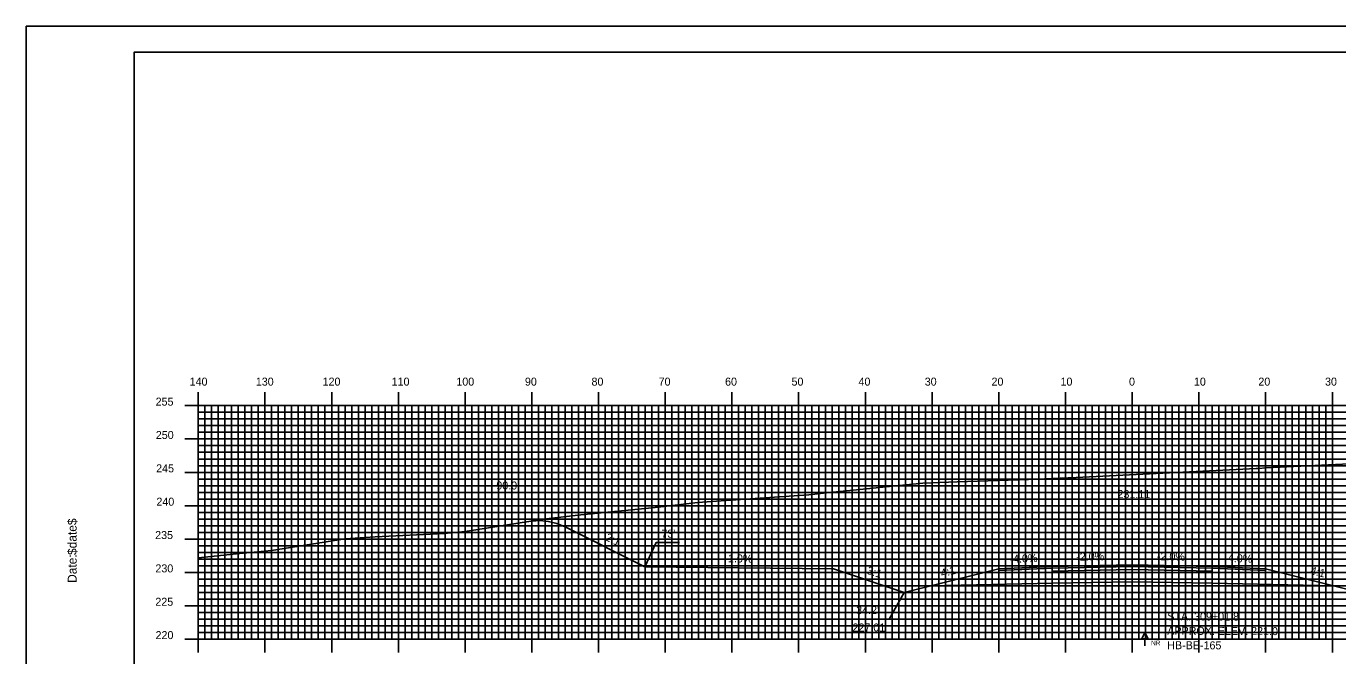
# Model space of a CAD drawing. Extents: x 1817670 to 1818013, y 442591 to 442811.
# Drawn here: x 1817669.8 to 1817866.4, y 442716.2 to 442810.5 of the extents above; entities that cross this region are included whole.
import ezdxf

# ---------------------------------------------------------------- set-up
doc = ezdxf.new("R2010")
doc.units = 0
for name, color, linetype in [('ANNOTATION', 7, 'Continuous'), ('BORDER', 7, 'Continuous'), ('BORING - NO REFUSAL', 7, 'Continuous'), ('D_Roadway_Centerline', 7, 'Continuous'), ('D_Roadway_Centerline_Text', 7, 'Continuous'), ('D_Roadway_Edge_Shoulder', 7, 'Continuous'), ('D_Roadway_Edge_TW', 7, 'Continuous'), ('D_Roadway_Pavement', 7, 'Continuous'), ('D_Roadway_SlopeLines', 7, 'Continuous'), ('D_Roadway_SubGrade', 7, 'Continuous'), ('D_Text_Standard', 7, 'Continuous'), ('H_V ANNOTATION', 7, 'Continuous'), ('MAJOR', 7, 'Continuous'), ('MINOR', 7, 'Continuous'), ('PLOT BOUNDARY', 7, 'Continuous'), ('S_Roadway_Centerline', 7, 'Continuous')]:
    doc.layers.add(name, color=color, linetype=linetype)

msp = doc.modelspace()

# ---------------------------------------------------------------- linework, layer by layer
at = {"layer": 'ANNOTATION'}
for points in [[(1817767.73, 442733.15), (1817764.23, 442733.15), (1817762.56, 442729.5)], [(1817793.49, 442721.68), (1817799.18, 442721.68), (1817801.44, 442725.67)]]:
    msp.add_lwpolyline(points, dxfattribs=at)
at = {"layer": 'BORDER'}
msp.add_lwpolyline([(1817686.01, 442596.67), (1818006.01, 442596.67), (1818006.01, 442806.67), (1817686.01, 442806.67)], close=True, dxfattribs=at)
at = {"layer": 'BORING - NO REFUSAL'}
for p, q in [((1817837.99, 442719.67), (1817837.03, 442719.67)), ((1817837.51, 442718.71), (1817837.51, 442717.65))]:
    msp.add_line(p, q, dxfattribs=at)
msp.add_lwpolyline([(1817837.51, 442719.67), (1817837.99, 442718.71), (1817837.03, 442718.71)], close=True, dxfattribs=at)
at = {"layer": 'D_Roadway_Centerline'}
msp.add_lwpolyline([(1817745.61, 442736.37), (1817746.86, 442736.45), (1817748.11, 442736.32), (1817749.36, 442736), (1817750.61, 442735.48), (1817762.56, 442729.5), (1817790.81, 442729.22), (1817801.44, 442725.67), (1817805.44, 442726.67), (1817815.61, 442729.22), (1817823.61, 442729.54), (1817835.61, 442729.78), (1817847.61, 442729.54), (1817855.61, 442729.22), (1817865.79, 442726.67), (1817869.79, 442725.67), (1817880.42, 442729.22), (1817887.92, 442729.29), (1817920.61, 442745.64), (1817921.86, 442746.19), (1817923.11, 442746.59), (1817924.36, 442746.83), (1817925.61, 442746.93)], dxfattribs=at)
at = {"layer": 'D_Roadway_Edge_Shoulder'}
for points in [[(1817823.61, 442729.54), (1817815.61, 442729.22), (1817815.61, 442728.97), (1817823.61, 442729.29)], [(1817847.61, 442729.54), (1817855.61, 442729.22), (1817855.61, 442728.97), (1817847.61, 442729.29)]]:
    msp.add_lwpolyline(points, close=True, dxfattribs=at)
at = {"layer": 'D_Roadway_Edge_TW'}
msp.add_lwpolyline([(1817823.61, 442729.29), (1817823.61, 442729.54), (1817835.61, 442729.78), (1817847.61, 442729.54), (1817847.61, 442729.29), (1817835.61, 442729.53)], close=True, dxfattribs=at)
at = {"layer": 'D_Roadway_Pavement'}
msp.add_lwpolyline([(1817823.61, 442728.87), (1817823.61, 442729.29), (1817835.61, 442729.53), (1817847.61, 442729.29), (1817847.61, 442728.87), (1817835.61, 442729.11)], close=True, dxfattribs=at)
at = {"layer": 'D_Roadway_SlopeLines'}
for points in [[(1817790.81, 442729.22), (1817762.56, 442729.5), (1817750.61, 442735.48), (1817749.36, 442736), (1817748.11, 442736.32), (1817746.86, 442736.45), (1817745.61, 442736.37)], [(1817801.44, 442725.67), (1817790.81, 442729.22)], [(1817815.61, 442729.22), (1817801.44, 442725.67)], [(1817855.61, 442729.22), (1817869.79, 442725.67)]]:
    msp.add_lwpolyline(points, dxfattribs=at)
at = {"layer": 'D_Roadway_SubGrade'}
msp.add_lwpolyline([(1817823.61, 442727.04), (1817805.44, 442726.67), (1817815.61, 442729.22), (1817815.61, 442728.97), (1817823.61, 442729.29), (1817835.61, 442729.53), (1817847.61, 442729.29), (1817855.61, 442728.97), (1817855.61, 442729.22), (1817865.79, 442726.67), (1817847.61, 442727.04), (1817835.61, 442727.28)], close=True, dxfattribs=at)
at = {"layer": 'MAJOR'}
for p, q in [((1817695.61, 442755.67), (1817695.61, 442753.67)), ((1817705.61, 442755.67), (1817705.61, 442753.67)), ((1817715.61, 442755.67), (1817715.61, 442753.67)), ((1817725.61, 442755.67), (1817725.61, 442753.67)), ((1817735.61, 442755.67), (1817735.61, 442753.67)), ((1817745.61, 442755.67), (1817745.61, 442753.67)), ((1817755.61, 442755.67), (1817755.61, 442753.67)), ((1817765.61, 442755.67), (1817765.61, 442753.67)), ((1817775.61, 442755.67), (1817775.61, 442753.67)), ((1817785.61, 442755.67), (1817785.61, 442753.67)), ((1817795.61, 442755.67), (1817795.61, 442753.67)), ((1817805.61, 442755.67), (1817805.61, 442753.67)), ((1817815.61, 442755.67), (1817815.61, 442753.67)), ((1817825.61, 442755.67), (1817825.61, 442753.67)), ((1817835.61, 442755.67), (1817835.61, 442753.67)), ((1817845.61, 442755.67), (1817845.61, 442753.67)), ((1817855.61, 442755.67), (1817855.61, 442753.67)), ((1817865.61, 442755.67), (1817865.61, 442753.67)), ((1817693.61, 442753.67), (1817695.61, 442753.67)), ((1817695.61, 442753.67), (1817975.61, 442753.67)), ((1817695.61, 442718.67), (1817695.61, 442753.67)), ((1817695.61, 442718.67), (1817695.61, 442753.67)), ((1817695.61, 442753.67), (1817975.61, 442753.67)), ((1817705.61, 442718.67), (1817705.61, 442753.67)), ((1817715.61, 442718.67), (1817715.61, 442753.67)), ((1817725.61, 442718.67), (1817725.61, 442753.67)), ((1817735.61, 442718.67), (1817735.61, 442753.67)), ((1817745.61, 442718.67), (1817745.61, 442753.67)), ((1817755.61, 442718.67), (1817755.61, 442753.67)), ((1817765.61, 442718.67), (1817765.61, 442753.67)), ((1817775.61, 442718.67), (1817775.61, 442753.67)), ((1817785.61, 442718.67), (1817785.61, 442753.67)), ((1817795.61, 442718.67), (1817795.61, 442753.67)), ((1817805.61, 442718.67), (1817805.61, 442753.67)), ((1817815.61, 442718.67), (1817815.61, 442753.67)), ((1817825.61, 442718.67), (1817825.61, 442753.67)), ((1817835.61, 442718.67), (1817835.61, 442753.67)), ((1817845.61, 442718.67), (1817845.61, 442753.67)), ((1817855.61, 442718.67), (1817855.61, 442753.67)), ((1817865.61, 442718.67), (1817865.61, 442753.67)), ((1817693.61, 442748.67), (1817695.61, 442748.67)), ((1817695.61, 442748.67), (1817975.61, 442748.67)), ((1817693.61, 442743.67), (1817695.61, 442743.67)), ((1817695.61, 442743.67), (1817975.61, 442743.67)), ((1817693.61, 442738.67), (1817695.61, 442738.67)), ((1817695.61, 442738.67), (1817975.61, 442738.67)), ((1817693.61, 442733.67), (1817695.61, 442733.67)), ((1817695.61, 442733.67), (1817975.61, 442733.67)), ((1817693.61, 442728.67), (1817695.61, 442728.67)), ((1817695.61, 442728.67), (1817975.61, 442728.67)), ((1817693.61, 442723.67), (1817695.61, 442723.67)), ((1817695.61, 442723.67), (1817975.61, 442723.67)), ((1817693.61, 442718.67), (1817695.61, 442718.67)), ((1817695.61, 442718.67), (1817975.61, 442718.67)), ((1817695.61, 442718.67), (1817975.61, 442718.67)), ((1817695.61, 442716.66), (1817695.61, 442718.67)), ((1817705.61, 442716.66), (1817705.61, 442718.67)), ((1817715.61, 442716.66), (1817715.61, 442718.67)), ((1817725.61, 442716.66), (1817725.61, 442718.67)), ((1817735.61, 442716.66), (1817735.61, 442718.67)), ((1817745.61, 442716.66), (1817745.61, 442718.67)), ((1817755.61, 442716.66), (1817755.61, 442718.67)), ((1817765.61, 442716.66), (1817765.61, 442718.67)), ((1817775.61, 442716.66), (1817775.61, 442718.67)), ((1817785.61, 442716.66), (1817785.61, 442718.67)), ((1817795.61, 442716.66), (1817795.61, 442718.67)), ((1817805.61, 442716.66), (1817805.61, 442718.67)), ((1817815.61, 442716.66), (1817815.61, 442718.67)), ((1817825.61, 442716.66), (1817825.61, 442718.67)), ((1817835.61, 442716.66), (1817835.61, 442718.67)), ((1817845.61, 442716.66), (1817845.61, 442718.67)), ((1817855.61, 442716.66), (1817855.61, 442718.67)), ((1817865.61, 442716.66), (1817865.61, 442718.67))]:
    msp.add_line(p, q, dxfattribs=at)
at = {"layer": 'MINOR'}
for p, q in [((1817696.61, 442718.67), (1817696.61, 442753.67)), ((1817697.61, 442718.67), (1817697.61, 442753.67)), ((1817698.61, 442718.67), (1817698.61, 442753.67)), ((1817699.61, 442718.67), (1817699.61, 442753.67)), ((1817700.61, 442718.67), (1817700.61, 442753.67)), ((1817701.61, 442718.67), (1817701.61, 442753.67)), ((1817702.61, 442718.67), (1817702.61, 442753.67)), ((1817703.61, 442718.67), (1817703.61, 442753.67)), ((1817704.61, 442718.67), (1817704.61, 442753.67)), ((1817706.61, 442718.67), (1817706.61, 442753.67)), ((1817707.61, 442718.67), (1817707.61, 442753.67)), ((1817708.61, 442718.67), (1817708.61, 442753.67)), ((1817709.61, 442718.67), (1817709.61, 442753.67)), ((1817710.61, 442718.67), (1817710.61, 442753.67)), ((1817711.61, 442718.67), (1817711.61, 442753.67)), ((1817712.61, 442718.67), (1817712.61, 442753.67)), ((1817713.61, 442718.67), (1817713.61, 442753.67)), ((1817714.61, 442718.67), (1817714.61, 442753.67)), ((1817716.61, 442718.67), (1817716.61, 442753.67)), ((1817717.61, 442718.67), (1817717.61, 442753.67)), ((1817718.61, 442718.67), (1817718.61, 442753.67)), ((1817719.61, 442718.67), (1817719.61, 442753.67)), ((1817720.61, 442718.67), (1817720.61, 442753.67)), ((1817721.61, 442718.67), (1817721.61, 442753.67)), ((1817722.61, 442718.67), (1817722.61, 442753.67)), ((1817723.61, 442718.67), (1817723.61, 442753.67)), ((1817724.61, 442718.67), (1817724.61, 442753.67)), ((1817726.61, 442718.67), (1817726.61, 442753.67)), ((1817727.61, 442718.67), (1817727.61, 442753.67)), ((1817728.61, 442718.67), (1817728.61, 442753.67)), ((1817729.61, 442718.67), (1817729.61, 442753.67)), ((1817730.61, 442718.67), (1817730.61, 442753.67)), ((1817731.61, 442718.67), (1817731.61, 442753.67)), ((1817732.61, 442718.67), (1817732.61, 442753.67)), ((1817733.61, 442718.67), (1817733.61, 442753.67)), ((1817734.61, 442718.67), (1817734.61, 442753.67)), ((1817736.61, 442718.67), (1817736.61, 442753.67)), ((1817737.61, 442718.67), (1817737.61, 442753.67)), ((1817738.61, 442718.67), (1817738.61, 442753.67)), ((1817739.61, 442718.67), (1817739.61, 442753.67)), ((1817740.61, 442718.67), (1817740.61, 442753.67)), ((1817741.61, 442718.67), (1817741.61, 442753.67)), ((1817742.61, 442718.67), (1817742.61, 442753.67)), ((1817743.61, 442718.67), (1817743.61, 442753.67)), ((1817744.61, 442718.67), (1817744.61, 442753.67)), ((1817746.61, 442718.67), (1817746.61, 442753.67)), ((1817747.61, 442718.67), (1817747.61, 442753.67)), ((1817748.61, 442718.67), (1817748.61, 442753.67)), ((1817749.61, 442718.67), (1817749.61, 442753.67)), ((1817750.61, 442718.67), (1817750.61, 442753.67)), ((1817751.61, 442718.67), (1817751.61, 442753.67)), ((1817752.61, 442718.67), (1817752.61, 442753.67)), ((1817753.61, 442718.67), (1817753.61, 442753.67)), ((1817754.61, 442718.67), (1817754.61, 442753.67)), ((1817756.61, 442718.67), (1817756.61, 442753.67)), ((1817757.61, 442718.67), (1817757.61, 442753.67)), ((1817758.61, 442718.67), (1817758.61, 442753.67)), ((1817759.61, 442718.67), (1817759.61, 442753.67)), ((1817760.61, 442718.67), (1817760.61, 442753.67)), ((1817761.61, 442718.67), (1817761.61, 442753.67)), ((1817762.61, 442718.67), (1817762.61, 442753.67)), ((1817763.61, 442718.67), (1817763.61, 442753.67)), ((1817764.61, 442718.67), (1817764.61, 442753.67)), ((1817766.61, 442718.67), (1817766.61, 442753.67)), ((1817767.61, 442718.67), (1817767.61, 442753.67)), ((1817768.61, 442718.67), (1817768.61, 442753.67)), ((1817769.61, 442718.67), (1817769.61, 442753.67)), ((1817770.61, 442718.67), (1817770.61, 442753.67)), ((1817771.61, 442718.67), (1817771.61, 442753.67)), ((1817772.61, 442718.67), (1817772.61, 442753.67)), ((1817773.61, 442718.67), (1817773.61, 442753.67)), ((1817774.61, 442718.67), (1817774.61, 442753.67)), ((1817776.61, 442718.67), (1817776.61, 442753.67)), ((1817777.61, 442718.67), (1817777.61, 442753.67)), ((1817778.61, 442718.67), (1817778.61, 442753.67)), ((1817779.61, 442718.67), (1817779.61, 442753.67)), ((1817780.61, 442718.67), (1817780.61, 442753.67)), ((1817781.61, 442718.67), (1817781.61, 442753.67)), ((1817782.61, 442718.67), (1817782.61, 442753.67)), ((1817783.61, 442718.67), (1817783.61, 442753.67)), ((1817784.61, 442718.67), (1817784.61, 442753.67)), ((1817786.61, 442718.67), (1817786.61, 442753.67)), ((1817787.61, 442718.67), (1817787.61, 442753.67)), ((1817788.61, 442718.67), (1817788.61, 442753.67)), ((1817789.61, 442718.67), (1817789.61, 442753.67)), ((1817790.61, 442718.67), (1817790.61, 442753.67)), ((1817791.61, 442718.67), (1817791.61, 442753.67)), ((1817792.61, 442718.67), (1817792.61, 442753.67)), ((1817793.61, 442718.67), (1817793.61, 442753.67)), ((1817794.61, 442718.67), (1817794.61, 442753.67)), ((1817796.61, 442718.67), (1817796.61, 442753.67)), ((1817797.61, 442718.67), (1817797.61, 442753.67)), ((1817798.61, 442718.67), (1817798.61, 442753.67)), ((1817799.61, 442718.67), (1817799.61, 442753.67)), ((1817800.61, 442718.67), (1817800.61, 442753.67)), ((1817801.61, 442718.67), (1817801.61, 442753.67)), ((1817802.61, 442718.67), (1817802.61, 442753.67)), ((1817803.61, 442718.67), (1817803.61, 442753.67)), ((1817804.61, 442718.67), (1817804.61, 442753.67)), ((1817806.61, 442718.67), (1817806.61, 442753.67)), ((1817807.61, 442718.67), (1817807.61, 442753.67)), ((1817808.61, 442718.67), (1817808.61, 442753.67)), ((1817809.61, 442718.67), (1817809.61, 442753.67)), ((1817810.61, 442718.67), (1817810.61, 442753.67)), ((1817811.61, 442718.67), (1817811.61, 442753.67)), ((1817812.61, 442718.67), (1817812.61, 442753.67)), ((1817813.61, 442718.67), (1817813.61, 442753.67)), ((1817814.61, 442718.67), (1817814.61, 442753.67)), ((1817816.61, 442718.67), (1817816.61, 442753.67)), ((1817817.61, 442718.67), (1817817.61, 442753.67)), ((1817818.61, 442718.67), (1817818.61, 442753.67)), ((1817819.61, 442718.67), (1817819.61, 442753.67)), ((1817820.61, 442718.67), (1817820.61, 442753.67)), ((1817821.61, 442718.67), (1817821.61, 442753.67)), ((1817822.61, 442718.67), (1817822.61, 442753.67)), ((1817823.61, 442718.67), (1817823.61, 442753.67)), ((1817824.61, 442718.67), (1817824.61, 442753.67)), ((1817826.61, 442718.67), (1817826.61, 442753.67)), ((1817827.61, 442718.67), (1817827.61, 442753.67)), ((1817828.61, 442718.67), (1817828.61, 442753.67)), ((1817829.61, 442718.67), (1817829.61, 442753.67)), ((1817830.61, 442718.67), (1817830.61, 442753.67)), ((1817831.61, 442718.67), (1817831.61, 442753.67)), ((1817832.61, 442718.67), (1817832.61, 442753.67)), ((1817833.61, 442718.67), (1817833.61, 442753.67)), ((1817834.61, 442718.67), (1817834.61, 442753.67)), ((1817836.61, 442718.67), (1817836.61, 442753.67)), ((1817837.61, 442718.67), (1817837.61, 442753.67)), ((1817838.61, 442718.67), (1817838.61, 442753.67)), ((1817839.61, 442718.67), (1817839.61, 442753.67)), ((1817840.61, 442718.67), (1817840.61, 442753.67)), ((1817841.61, 442718.67), (1817841.61, 442753.67)), ((1817842.61, 442718.67), (1817842.61, 442753.67)), ((1817843.61, 442718.67), (1817843.61, 442753.67)), ((1817844.61, 442718.67), (1817844.61, 442753.67)), ((1817846.61, 442718.67), (1817846.61, 442753.67)), ((1817847.61, 442718.67), (1817847.61, 442753.67)), ((1817848.61, 442718.67), (1817848.61, 442753.67)), ((1817849.61, 442718.67), (1817849.61, 442753.67)), ((1817850.61, 442718.67), (1817850.61, 442753.67)), ((1817851.61, 442718.67), (1817851.61, 442753.67)), ((1817852.61, 442718.67), (1817852.61, 442753.67)), ((1817853.61, 442718.67), (1817853.61, 442753.67)), ((1817854.61, 442718.67), (1817854.61, 442753.67)), ((1817856.61, 442718.67), (1817856.61, 442753.67)), ((1817857.61, 442718.67), (1817857.61, 442753.67)), ((1817858.61, 442718.67), (1817858.61, 442753.67)), ((1817859.61, 442718.67), (1817859.61, 442753.67)), ((1817860.61, 442718.67), (1817860.61, 442753.67)), ((1817861.61, 442718.67), (1817861.61, 442753.67)), ((1817862.61, 442718.67), (1817862.61, 442753.67)), ((1817863.61, 442718.67), (1817863.61, 442753.67)), ((1817864.61, 442718.67), (1817864.61, 442753.67)), ((1817695.61, 442752.67), (1817975.61, 442752.67)), ((1817695.61, 442752.67), (1817697.62, 442752.67)), ((1817695.61, 442751.67), (1817975.61, 442751.67)), ((1817695.61, 442751.67), (1817697.62, 442751.67)), ((1817695.61, 442750.67), (1817975.61, 442750.67)), ((1817695.61, 442750.67), (1817697.62, 442750.67)), ((1817695.61, 442749.67), (1817975.61, 442749.67)), ((1817695.61, 442749.67), (1817697.62, 442749.67)), ((1817695.61, 442747.67), (1817975.61, 442747.67)), ((1817695.61, 442747.67), (1817697.62, 442747.67)), ((1817695.61, 442746.67), (1817975.61, 442746.67)), ((1817695.61, 442746.67), (1817697.62, 442746.67)), ((1817695.61, 442745.67), (1817975.61, 442745.67)), ((1817695.61, 442745.67), (1817697.62, 442745.67)), ((1817695.61, 442744.67), (1817975.61, 442744.67)), ((1817695.61, 442744.67), (1817697.62, 442744.67)), ((1817695.61, 442742.67), (1817975.61, 442742.67)), ((1817695.61, 442742.67), (1817697.62, 442742.67)), ((1817695.61, 442741.67), (1817975.61, 442741.67)), ((1817695.61, 442741.67), (1817697.62, 442741.67)), ((1817695.61, 442740.67), (1817975.61, 442740.67)), ((1817695.61, 442740.67), (1817697.62, 442740.67)), ((1817695.61, 442739.67), (1817975.61, 442739.67)), ((1817695.61, 442739.67), (1817697.62, 442739.67)), ((1817695.61, 442737.67), (1817975.61, 442737.67)), ((1817695.61, 442737.67), (1817697.62, 442737.67)), ((1817695.61, 442736.67), (1817975.61, 442736.67)), ((1817695.61, 442736.67), (1817697.62, 442736.67)), ((1817695.61, 442735.67), (1817975.61, 442735.67)), ((1817695.61, 442735.67), (1817697.62, 442735.67)), ((1817695.61, 442734.67), (1817975.61, 442734.67)), ((1817695.61, 442734.67), (1817697.62, 442734.67)), ((1817695.61, 442732.67), (1817975.61, 442732.67)), ((1817695.61, 442732.67), (1817697.62, 442732.67)), ((1817695.61, 442731.67), (1817975.61, 442731.67)), ((1817695.61, 442731.67), (1817697.62, 442731.67)), ((1817695.61, 442730.67), (1817975.61, 442730.67)), ((1817695.61, 442730.67), (1817697.62, 442730.67)), ((1817695.61, 442729.67), (1817975.61, 442729.67)), ((1817695.61, 442729.67), (1817697.62, 442729.67)), ((1817695.61, 442727.67), (1817975.61, 442727.67)), ((1817695.61, 442727.67), (1817697.62, 442727.67)), ((1817695.61, 442726.67), (1817975.61, 442726.67)), ((1817695.61, 442726.67), (1817697.62, 442726.67)), ((1817695.61, 442725.67), (1817975.61, 442725.67)), ((1817695.61, 442725.67), (1817697.62, 442725.67)), ((1817695.61, 442724.67), (1817975.61, 442724.67)), ((1817695.61, 442724.67), (1817697.62, 442724.67)), ((1817695.61, 442722.67), (1817975.61, 442722.67)), ((1817695.61, 442722.67), (1817697.62, 442722.67)), ((1817695.61, 442721.67), (1817975.61, 442721.67)), ((1817695.61, 442721.67), (1817697.62, 442721.67)), ((1817695.61, 442720.67), (1817975.61, 442720.67)), ((1817695.61, 442720.67), (1817697.62, 442720.67)), ((1817695.61, 442719.67), (1817975.61, 442719.67)), ((1817695.61, 442719.67), (1817697.62, 442719.67))]:
    msp.add_line(p, q, dxfattribs=at)
at = {"layer": 'PLOT BOUNDARY'}
msp.add_lwpolyline([(1817669.83, 442590.55), (1818009.83, 442590.55), (1818009.83, 442810.55), (1817669.83, 442810.55)], close=True, dxfattribs=at)
at = {"layer": 'S_Roadway_Centerline'}
msp.add_lwpolyline([(1817695.61, 442730.85), (1817701.33, 442731.43), (1817706.59, 442731.93), (1817717.62, 442733.72), (1817722.14, 442734.01), (1817732.47, 442734.51), (1817735.6, 442734.82), (1817747.35, 442736.64), (1817752.97, 442737.28), (1817764.12, 442738.42), (1817770.51, 442739.15), (1817773.98, 442739.38), (1817786.4, 442740.26), (1817787.14, 442740.31), (1817789.8, 442740.61), (1817804.21, 442742.05), (1817809.38, 442742.27), (1817820.08, 442742.6), (1817827.23, 442742.88), (1817854.18, 442744.26), (1817854.56, 442744.27), (1817855.7, 442744.33), (1817871.29, 442745.12)], dxfattribs=at)

# ---------------------------------------------------------------- texts
at = {"layer": 'ANNOTATION'}
for s, rotation, p in [('2:1', 333.4349, (1817756.52, 442733.56)), ('1.0%', 359.4271, (1817775.02, 442730.18)), ('-4.0%', 2.2906, (1817817.24, 442730.08)), ('-2.0%', 1.1458, (1817827.22, 442730.41)), ('-2.0%', 358.8542, (1817839.3, 442730.5)), ('-4.0%', 357.7094, (1817849.4, 442730.27)), ('3:1', 341.5651, (1817795.73, 442728.49)), ('4:1', 14.0362, (1817807.06, 442727.94)), ('4:1', 345.9638, (1817862.21, 442728.43))]:
    msp.add_text(s, height=1.2, rotation=rotation, dxfattribs=at).set_placement(p)
for s, p in [("73'", (1817765.03, 442733.88)), ("34.2'", (1817794.23, 442722.41)), ('227.01', (1817793.68, 442719.81))]:
    msp.add_text(s, height=1.2, dxfattribs=at).set_placement(p)
at = {"layer": 'BORDER'}
for s, p in [('$date$', (1817677.38, 442731.28)), ('Date:', (1817677.38, 442727.1))]:
    msp.add_text(s, height=1.339, rotation=90, dxfattribs=at).set_placement(p)
at = {"layer": 'BORING - NO REFUSAL'}
for s, p in [('STA. 309+01.8', (1817840.87, 442721.48)), ('APPROX. ELEV. 221.0', (1817840.86, 442719.32)), ('HB-BE-165', (1817840.86, 442717.16))]:
    msp.add_text(s, height=1.2, rotation=359.8142, dxfattribs=at).set_placement(p)
msp.add_text('NR', height=0.7, dxfattribs=at).set_placement((1817838.44, 442717.75))
at = {"layer": 'D_Roadway_Centerline'}
for s, p in [('C', (1817835.61, 442729.78)), ('L', (1817835.61, 442729.77))]:
    msp.add_text(s, height=0.0146, dxfattribs=at).set_placement(p)
at = {"layer": 'D_Roadway_Centerline_Text'}
msp.add_text('231.11', height=1.2, dxfattribs=at).set_placement((1817833.4, 442739.81))
at = {"layer": 'D_Text_Standard'}
msp.add_text("90.0'", height=1.2, dxfattribs=at).set_placement((1817740.29, 442741.1))
at = {"layer": 'H_V ANNOTATION'}
for s, p in [('140', (1817694.32, 442756.67)), ('130', (1817704.24, 442756.67)), ('120', (1817714.25, 442756.67)), ('110', (1817724.6, 442756.67)), ('100', (1817734.3, 442756.67)), ('90', (1817744.58, 442756.67)), ('80', (1817754.56, 442756.67)), ('70', (1817764.62, 442756.67)), ('60', (1817774.58, 442756.67)), ('50', (1817784.54, 442756.67)), ('40', (1817794.58, 442756.67)), ('30', (1817804.51, 442756.67)), ('20', (1817814.52, 442756.67)), ('10', (1817824.86, 442756.67)), ('0', (1817835.13, 442756.67)), ('10', (1817844.86, 442756.67)), ('20', (1817854.52, 442756.67)), ('30', (1817864.51, 442756.67)), ('255', (1817689.22, 442753.67)), ('250', (1817689.25, 442748.67)), ('245', (1817689.3, 442743.67)), ('240', (1817689.34, 442738.67)), ('235', (1817689.15, 442733.67)), ('230', (1817689.19, 442728.67)), ('225', (1817689.18, 442723.67)), ('220', (1817689.21, 442718.67))]:
    msp.add_text(s, height=1.2, dxfattribs=at).set_placement(p)
at = {"layer": 'MAJOR'}
msp.add_text('-', height=0.012, dxfattribs=at).set_placement((1817695.6, 442718.67))

doc.saveas('drawing.dxf')
